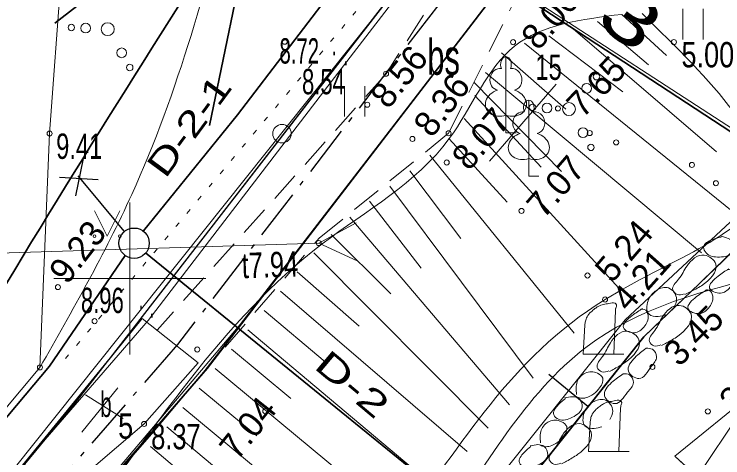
# Model space of a CAD drawing. Extents: x 514052 to 514314, y 297701 to 297876.
# Drawn here: x 514248.88 to 514262.86, y 297796.71 to 297805.47 of the extents above; entities that cross this region are included whole.
import ezdxf
from ezdxf.enums import TextEntityAlignment as Align

# ---------------------------------------------------------------- set-up
doc = ezdxf.new("R2010")
doc.units = 0
doc.header["$LTSCALE"] = 0.2
for name, pattern in [('DOT_DASHED', [7.7, 5, -1.2, 0.3, -1.2]), ('DOTTED', [1.5, 0.3, -1.2]), ('MEDIUM_DASHED', [4.5, 3, -1.5])]:
    doc.linetypes.add(name, pattern=pattern)
for name, color, linetype, lineweight in [('1', 7, 'Continuous', 13), ('11', 7, 'Continuous', 35), ('19', 7, 'Continuous', 25), ('25', 7, 'Continuous', 13), ('28', 7, 'Continuous', 13), ('3', 7, 'Continuous', 13), ('30', 7, 'Continuous', 13), ('35', 7, 'Continuous', 25), ('4', 7, 'Continuous', 13), ('5', 7, 'Continuous', 13), ('55', 7, 'Continuous', 13), ('56', 7, 'Continuous', 13), ('57', 7, 'DOTTED', 13), ('6', 7, 'Continuous', 13), ('61', 7, 'Continuous', 13), ('62', 7, 'Continuous', 13), ('63', 7, 'Continuous', 13)]:
    doc.layers.add(name, color=color, linetype=linetype, lineweight=lineweight)
for name, color, linetype in [('10', 7, 'Continuous'), ('12', 7, 'Continuous'), ('15', 7, 'Continuous'), ('8', 7, 'Continuous')]:
    doc.layers.add(name, color=color, linetype=linetype)

msp = doc.modelspace()

# ---------------------------------------------------------------- linework, layer by layer
at = {"layer": '1'}
for p, q in [((514260.862, 297805.466), (514261.747, 297804.65)), ((514260.382, 297805.324), (514261.389, 297804.471)), ((514259.903, 297805.181), (514262.732, 297802.751)), ((514259.424, 297805.039), (514260.887, 297803.934)), ((514258.944, 297804.897), (514263.46, 297801.234)), ((514258.488, 297804.703), (514259.759, 297803.593)), ((514258.178, 297804.315), (514262.439, 297800.756)), ((514257.964, 297803.863), (514259.276, 297802.447)), ((514257.752, 297803.41), (514260.804, 297800.061)), ((514257.457, 297803.009), (514258.604, 297801.754)), ((514257.079, 297802.682), (514259.927, 297799.171)), ((514256.685, 297802.375), (514257.691, 297801.041)), ((514256.285, 297802.075), (514259.118, 297798.277)), ((514255.886, 297801.774), (514256.907, 297800.454)), ((514255.498, 297801.458), (514258.648, 297797.755)), ((514255.13, 297801.12), (514256.31, 297799.945)), ((514254.791, 297800.753), (514258.23, 297797.292)), ((514254.46, 297800.378), (514255.685, 297799.307)), ((514254.132, 297800), (514257.81, 297796.829)), ((514253.807, 297799.62), (514255.009, 297798.603)), ((514253.484, 297799.238), (514257.177, 297796.134)), ((514253.163, 297798.855), (514254.335, 297797.88)), ((514252.844, 297798.47), (514256.52, 297795.422)), ((514252.525, 297798.085), (514253.664, 297797.141)), ((514252.206, 297797.701), (514255.837, 297794.686)), ((514251.886, 297797.316), (514252.993, 297796.394)), ((514251.565, 297796.933), (514255.194, 297793.878))]:
    msp.add_line(p, q, dxfattribs=at)
msp.add_circle((514254.16, 297803.109), 0.1827, dxfattribs=at)
msp.add_spline([(514260.862, 297805.466), (514258.749, 297804.839), (514257.459, 297803.011), (514254.953, 297800.933), (514250.105, 297795.245), (514240.136, 297784.718), (514236.07, 297778.812), (514235.246, 297774.955), (514233.92, 297771.109), (514234.456, 297764.804)], degree=3, dxfattribs=at)
at = {"layer": '11'}
msp.add_line((514256.643, 297807.328), (514264.954, 297801.867), dxfattribs=at)
for points in [[(514251.427, 297801.19), (514253.28, 297803.48), (514255.373, 297806.228)], [(514243.591, 297791.72), (514245.183, 297793.281), (514249.573, 297798.519), (514251.063, 297800.706)]]:
    msp.add_lwpolyline(points, dxfattribs=at)
at = {"layer": '19', "lineweight": 13}
msp.add_spline([(514243.205, 297765.058), (514242.936, 297773.769), (514245.025, 297781.038), (514246.54, 297783.925), (514249.054, 297787.013), (514257.225, 297795.21), (514260.154, 297798.886), (514267.863, 297801.516), (514273.305, 297805.826), (514276.583, 297807.615)], degree=3, dxfattribs=at)
at = {"layer": '25'}
for points in [[(514251.157, 297801.751), (514251.157, 297800.251), (514251.157, 297798.751)], [(514251.157, 297801.751), (514251.157, 297800.251), (514251.157, 297798.751)], [(514249.657, 297800.251), (514251.157, 297800.251), (514252.657, 297800.251)], [(514249.657, 297800.251), (514251.157, 297800.251), (514252.657, 297800.251)]]:
    msp.add_lwpolyline(points, dxfattribs=at)
at = {"layer": '28'}
msp.add_lwpolyline([(514255.622, 297801.347), (514254.884, 297800.949), (514255.645, 297800.598)], dxfattribs=at)
at = {"layer": '3'}
for p, q in [((514264.293, 297802.389), (514238.829, 297819.008)), ((514245.502, 297800.655), (514254.884, 297800.949))]:
    msp.add_line(p, q, dxfattribs=at)
at = {"layer": '30'}
msp.add_spline([(514249.384, 297798.494), (514251.195, 297801.909), (514253.241, 297808.298), (514253.999, 297811.552)], degree=3, dxfattribs=at)
at = {"layer": '35'}
msp.add_lwpolyline([(514231.97, 297771.331), (514233.541, 297774.128), (514233.667, 297780.485), (514240.255, 297787.177), (514246.843, 297793.868), (514250.774, 297798.68), (514254.387, 297803.352), (514256.058, 297805.511), (514258.694, 297808.915), (514260.151, 297809.248), (514268.632, 297811.186)], dxfattribs=at)
at = {"layer": '35', "lineweight": 35}
msp.add_lwpolyline([(514271.3, 297810.152), (514259.606, 297807.499), (514252.681, 297798.474), (514245.829, 297790.57), (514238.515, 297783.139), (514236.323, 297779.764), (514235.19, 297775.821), (514235.133, 297773.758), (514233.372, 297770.559)], dxfattribs=at)
at = {"layer": '4'}
for points in [[(514263.48, 297798.014), (514262.354, 297796.334), (514261.911, 297796.738)], [(514262.132, 297796.536), (514262.354, 297796.334), (514263.48, 297798.014), (514261.911, 297796.738)]]:
    msp.add_lwpolyline(points, close=True, dxfattribs=at)
at = {"layer": '5'}
for p, q in [((514262.068, 297804.972), (514262.068, 297805.572)), ((514262.468, 297804.972), (514262.468, 297805.572)), ((514258.579, 297804.626), (514258.579, 297803.473)), ((514258.669, 297804.394), (514258.668, 297804.395)), ((514255.392, 297803.448), (514255.392, 297804.048)), ((514255.792, 297803.448), (514255.792, 297804.048)), ((514259.029, 297803.772), (514259.029, 297802.619)), ((514258.579, 297803.473), (514258.579, 297803.126)), ((514259.119, 297803.54), (514259.118, 297803.541)), ((514258.579, 297803.126), (514258.779, 297803.126)), ((514259.029, 297802.619), (514259.029, 297802.272)), ((514259.029, 297802.272), (514259.229, 297802.272)), ((514260.704, 297798.757), (514260.738, 297799.622)), ((514260.704, 297798.757), (514260.104, 297798.757)), ((514260.704, 297798.757), (514260.904, 297798.757)), ((514260.807, 297796.832), (514260.841, 297797.697)), ((514260.807, 297796.832), (514260.207, 297796.832)), ((514260.807, 297796.832), (514261.007, 297796.832))]:
    msp.add_line(p, q, dxfattribs=at)
for points in [[(514250.462, 297801.587), (514250.712, 297801.087), (514250.962, 297801.587)], [(514260.135, 297799.33), (514260.104, 297798.757), (514260.404, 297798.757), (514260.704, 297798.757)], [(514260.238, 297797.405), (514260.207, 297796.832), (514260.507, 297796.832), (514260.807, 297796.832)]]:
    msp.add_lwpolyline(points, dxfattribs=at)
for centre, radius in [((514250.288, 297805.1939), 0.096), ((514250.7219, 297805.1731), 0.128), ((514250.0036, 297805.2074), 0.064), ((514250.9984, 297804.7063), 0.096), ((514251.1559, 297804.417), 0.064), ((514260.366, 297804.2345), 0.064), ((514260.1695, 297804.0028), 0.096), ((514259.1035, 297803.6294), 0.064), ((514259.388, 297803.6159), 0.096), ((514259.822, 297803.5952), 0.128), ((514260.0984, 297803.1283), 0.096), ((514260.2559, 297802.839), 0.064), ((514250.4621, 297801.0864), 0.028), ((514250.9621, 297801.0864), 0.0263)]:
    msp.add_circle(centre, radius, dxfattribs=at)
for centre, major_axis, ratio, start_param, end_param in [((514258.5794, 297804.4762), (0, -0.1499), 0.707107, 3.1453698, 5.2874846), ((514258.5785, 297804.4762), (0, -0.1499), 0.707107, 0.9957007, 3.1378155), ((514258.4507, 297804.1814), (-0.0387, -0.2124), 0.861323, 3.1415927, 6.2831853), ((514258.7072, 297804.1814), (0.0387, -0.2124), 0.861323, 6.2831853, 9.424778), ((514258.4894, 297803.7191), (0.3068, 0.0951), 0.814445, 1.5707963, 4.7520146), ((514258.6685, 297803.7191), (-0.3068, 0.0951), 0.814445, 1.5311707, 4.712389), ((514259.0294, 297803.6222), (0, -0.1499), 0.707107, 3.1453698, 5.2874846), ((514259.0285, 297803.6222), (0, -0.1499), 0.707107, 0.9957007, 3.1378155), ((514258.9007, 297803.3274), (-0.0387, -0.2124), 0.861323, 3.1415927, 6.2831853), ((514259.1572, 297803.3274), (0.0387, -0.2124), 0.861323, 6.2831853, 9.424778), ((514258.9394, 297802.8651), (0.3068, 0.0951), 0.814445, 1.5707963, 4.7520146), ((514259.1185, 297802.8651), (-0.3068, 0.0951), 0.814445, 1.5311707, 4.712389)]:
    msp.add_ellipse(centre, major_axis=major_axis, ratio=ratio, start_param=start_param, end_param=end_param, dxfattribs=at)
for points in [[(514260.738, 297799.622), (514260.742, 297799.653), (514260.745, 297799.664), (514260.76, 297799.726), (514260.73, 297799.761), (514260.608, 297799.755), (514260.504, 297799.737), (514260.398, 297799.698), (514260.333, 297799.654), (514260.258, 297799.59), (514260.178, 297799.492), (514260.147, 297799.403), (514260.135, 297799.329)], [(514260.841, 297797.697), (514260.845, 297797.728), (514260.848, 297797.739), (514260.863, 297797.801), (514260.833, 297797.836), (514260.711, 297797.83), (514260.607, 297797.812), (514260.501, 297797.773), (514260.436, 297797.729), (514260.361, 297797.665), (514260.281, 297797.567), (514260.25, 297797.478), (514260.238, 297797.404)]]:
    msp.add_spline(points, degree=3, dxfattribs=at)
at = {"layer": '55'}
msp.add_lwpolyline([(514217.339, 297769.84), (514231.97, 297771.331), (514233.541, 297774.128), (514233.602, 297778.964), (514248.877, 297796.499), (514258.817, 297808.985), (514270.863, 297811.577), (514272.894, 297813.849)], dxfattribs=at)
at = {"layer": '56'}
msp.add_lwpolyline([(514249.079, 297796.575), (514249.802, 297795.978), (514251.44, 297797.376), (514252.508, 297798.584), (514251.401, 297799.459)], close=True, dxfattribs=at)
at = {"layer": '57'}
msp.add_line((514249.886, 297798.666), (514258.975, 297809.539), dxfattribs=at)
at = {"layer": '6'}
for centre in [(514254.2148, 297804.9251), (514258.718, 297804.9162), (514261.892, 297804.9191), (514256.212, 297804.2922), (514255.8419, 297803.6801), (514259.6029, 297803.6072), (514249.5739, 297803.1122), (514256.7319, 297803.0042), (514257.448, 297803.1182), (514260.2319, 297803.1222), (514260.7529, 297802.9371), (514257.4109, 297802.5401), (514262.2479, 297802.4911), (514262.7215, 297802.1309), (514258.8849, 297801.5831), (514254.8839, 297800.9492), (514260.1879, 297800.3081), (514249.7388, 297800.0784), (514260.533, 297799.8342), (514250.462, 297799.4062), (514252.4889, 297798.8461), (514249.3839, 297798.4941), (514261.469, 297798.5021), (514253.8289, 297797.6282), (514262.562, 297797.624), (514251.4399, 297797.3761)]:
    msp.add_circle(centre, 0.05, dxfattribs=at)
at = {"layer": '61'}
msp.add_lwpolyline([(514246.843, 297793.868), (514250.081, 297797.789), (514258.694, 297808.915), (514270.983, 297811.723)], dxfattribs=at)
at = {"layer": '62'}
msp.add_spline([(514242.228, 297765.875), (514240.809, 297773.912), (514243.289, 297779.448), (514244.466, 297781.572), (514244.559, 297781.63), (514245.987, 297783.723), (514248.871, 297787.176), (514251.243, 297789.878), (514252.476, 297791.159), (514253.723, 297792.429), (514256.513, 297795.415), (514260.533, 297799.834), (514263.587, 297801.907), (514261.268, 297805.481)], degree=3, dxfattribs=at)
at = {"layer": '63'}
for p, q in [((514257.949, 297804.118), (514259.672, 297802.361)), ((514259.57, 297804.084), (514258.253, 297802.564)), ((514250.922, 297798.089), (514250.213, 297797.211)), ((514250.281, 297797.954), (514251.024, 297797.481))]:
    msp.add_line(p, q, dxfattribs=at)
at = {"layer": '63', "lineweight": 25}
for p, q in [((514250.237, 297802.622), (514250.089, 297801.883)), ((514249.769, 297802.253), (514250.532, 297802.204)), ((514251.049, 297801.185), (514250.138, 297802.278)), ((514260.196, 297797.718), (514259.422, 297798.35))]:
    msp.add_line(p, q, dxfattribs=at)
at = {"layer": '63', "lineweight": 35}
msp.add_line((514251.465, 297800.758), (514258.511, 297795.026), dxfattribs=at)
at = {"layer": '63'}
for points in [[(514240.25, 297797.788), (514240.461, 297794.955), (514244.254, 297792.763), (514245.158, 297793.439), (514249.384, 297798.494), (514249.574, 297803.112), (514249.804, 297806.229), (514250.567, 297808.046), (514251.305, 297808.79), (514254.642, 297812.211), (514253.566, 297813.059)], [(514241.033, 297787.835), (514244.727, 297791.588), (514248.123, 297795.505), (514251.519, 297799.422), (514255.132, 297804.131), (514258.746, 297808.841), (514264.857, 297810.227), (514270.968, 297811.614), (514271.3, 297810.152), (514259.609, 297807.499), (514256.144, 297802.987), (514253.336, 297799.341), (514249.255, 297794.522), (514245.829, 297790.57)], [(514246.248, 297791.053), (514247.856, 297792.907), (514251.587, 297797.176), (514252.569, 297798.349), (514254.104, 297800.332), (514255.107, 297801.628), (514257.105, 297804.234), (514259.609, 297807.499), (514265.761, 297808.894), (514271.304, 297810.15), (514273.327, 297806.65), (514267.17, 297803.809), (514264.799, 297803.032), (514260.928, 297799.431), (514257.141, 297794.684), (514253.744, 297790.866)]]:
    msp.add_lwpolyline(points, dxfattribs=at)
at = {"layer": '63', "linetype": 'MEDIUM_DASHED'}
for points in [[(514271.543, 297811.739), (514264.007, 297809.944), (514261.486, 297809.159), (514258.408, 297807.724), (514256.212, 297804.292), (514251.695, 297799.226)], [(514231.583, 297765.652), (514232.855, 297769.107), (514235.126, 297775.062), (514235.802, 297779.27), (514240.035, 297784.801), (514250.098, 297795.488), (514254.893, 297801.043), (514257.448, 297803.118), (514259.485, 297807.223), (514261.814, 297808.455), (514265.145, 297808.86), (514272.105, 297811.112)]]:
    msp.add_lwpolyline(points, dxfattribs=at)
at = {"layer": '63', "linetype": 'DOT_DASHED', "lineweight": 25}
for points in [[(514271.134, 297810.883), (514259.176, 297808.17), (514252.1, 297798.948), (514245.278, 297791.079), (514237.927, 297783.611), (514235.633, 297780.079), (514234.443, 297775.937), (514234.388, 297773.96), (514232.332, 297770.225), (514229.92, 297766.887)], [(514241.744, 297765.925), (514242.057, 297774.207), (514242.797, 297776.707), (514244.225, 297779.218), (514245.964, 297781.323), (514250.712, 297786.706), (514257.523, 297794.362), (514261.299, 297799.094), (514264.423, 297802.109), (514265.043, 297802.596), (514265.222, 297802.656), (514267.352, 297803.342), (514273.537, 297806.201)]]:
    msp.add_lwpolyline(points, dxfattribs=at)
at = {"layer": '63', "lineweight": 35}
for points in [[(514249.676, 297805.292), (514253.805, 297808.49), (514252.731, 297803.27)], [(514241.744, 297765.925), (514242.057, 297774.207), (514242.797, 297776.707), (514244.225, 297779.218), (514245.094, 297780.271), (514245.964, 297781.323), (514248.338, 297784.015), (514250.712, 297786.706), (514254.118, 297790.534), (514257.523, 297794.362), (514259.411, 297796.728), (514261.299, 297799.094), (514262.861, 297800.601), (514264.423, 297802.109), (514265.043, 297802.596), (514267.352, 297803.342), (514273.537, 297806.201)]]:
    msp.add_lwpolyline(points, dxfattribs=at)
at = {"layer": '63', "lineweight": 25}
msp.add_circle((514251.2418, 297800.9459), 0.3, dxfattribs=at)
at = {"layer": '63', "lineweight": 35}
msp.add_spline([(514235.586, 297788.069), (514238.834, 297789.344), (514246.139, 297795.966), (514248.394, 297799.596), (514253.835, 297808.327)], degree=3, dxfattribs=at)
at = {"layer": '63'}
for points in [[(514262.815, 297801.085), (514263.061, 297800.954), (514263.055, 297800.779), (514262.791, 297800.673), (514262.527, 297800.755), (514262.479, 297800.87), (514262.651, 297801.017), (514262.823, 297801.067)], [(514262.096, 297799.946), (514261.957, 297799.934), (514261.87, 297800.023), (514261.986, 297800.234), (514262.151, 297800.499), (514262.492, 297800.711), (514262.717, 297800.532), (514262.437, 297800.107), (514262.21, 297799.983), (514262.108, 297799.933)], [(514262.973, 297800.438), (514262.764, 297800.295), (514262.596, 297800.06), (514262.814, 297799.96), (514262.998, 297800.069), (514263.082, 297800.304), (514263.007, 297800.421), (514262.948, 297800.421)], [(514261.888, 297799.675), (514261.946, 297799.841), (514261.786, 297800.062), (514261.548, 297800.015), (514261.381, 297799.808), (514261.402, 297799.543), (514261.58, 297799.5), (514261.731, 297799.531)], [(514262.549, 297800.033), (514262.34, 297799.89), (514262.172, 297799.655), (514262.39, 297799.555), (514262.574, 297799.664), (514262.658, 297799.899), (514262.583, 297800.016), (514262.524, 297800.016)], [(514261.637, 297798.936), (514261.499, 297798.918), (514261.408, 297799.003), (514261.514, 297799.219), (514261.667, 297799.491), (514261.999, 297799.718), (514262.231, 297799.549), (514261.971, 297799.112), (514261.749, 297798.978), (514261.65, 297798.923)], [(514261.274, 297799.656), (514261.065, 297799.513), (514260.897, 297799.278), (514261.115, 297799.178), (514261.299, 297799.287), (514261.383, 297799.522), (514261.308, 297799.639), (514261.249, 297799.639)], [(514260.609, 297798.425), (514260.471, 297798.407), (514260.38, 297798.492), (514260.486, 297798.708), (514260.639, 297798.98), (514260.971, 297799.207), (514261.203, 297799.038), (514260.943, 297798.601), (514260.721, 297798.467), (514260.622, 297798.412)], [(514261.342, 297798.87), (514261.122, 297798.685), (514260.995, 297798.416), (514261.201, 297798.273), (514261.445, 297798.509), (514261.55, 297798.703), (514261.469, 297798.85), (514261.342, 297798.87)], [(514259.97, 297797.959), (514259.986, 297798.212), (514260.143, 297798.382), (514260.384, 297798.377), (514260.487, 297798.281), (514260.407, 297798.064), (514260.272, 297797.945), (514260.049, 297797.886), (514259.972, 297797.91)], [(514260.892, 297798.368), (514260.664, 297798.193), (514260.525, 297797.93), (514260.725, 297797.778), (514260.979, 297798.003), (514261.093, 297798.192), (514261.018, 297798.343), (514260.892, 297798.368)], [(514259.736, 297797.891), (514260.014, 297797.876), (514260.084, 297797.715), (514259.889, 297797.507), (514259.615, 297797.471), (514259.523, 297797.555), (514259.617, 297797.76), (514259.751, 297797.878)], [(514260.629, 297797.464), (514260.687, 297797.63), (514260.527, 297797.851), (514260.289, 297797.804), (514260.122, 297797.597), (514260.143, 297797.332), (514260.321, 297797.289), (514260.472, 297797.32)], [(514259.26, 297797.003), (514259.276, 297797.256), (514259.433, 297797.426), (514259.674, 297797.421), (514259.777, 297797.325), (514259.697, 297797.108), (514259.562, 297796.989), (514259.339, 297796.93), (514259.262, 297796.954)], [(514259.663, 297796.6), (514259.525, 297796.582), (514259.434, 297796.667), (514259.54, 297796.883), (514259.693, 297797.155), (514260.025, 297797.382), (514260.257, 297797.213), (514259.997, 297796.776), (514259.775, 297796.642), (514259.676, 297796.587)], [(514259.056, 297796.945), (514259.334, 297796.93), (514259.404, 297796.769), (514259.209, 297796.561), (514258.935, 297796.525), (514258.843, 297796.609), (514258.937, 297796.814), (514259.071, 297796.932)]]:
    msp.add_spline(points, degree=3, dxfattribs=at)

# ---------------------------------------------------------------- texts
at = {"layer": '10', "width": 0.65}
msp.add_text('bs', height=0.7, dxfattribs=at).set_placement((514257.349, 297804.272), align=Align.CENTER)
at = {"layer": '11'}
for s, rotation, width, p in [('t7.94', 1.795, 0.75, (514253.9292, 297800.2707)), ('D-2', 319.946, 1.5, (514255.3866, 297797.969))]:
    msp.add_text(s, height=0.5, rotation=rotation, dxfattribs=dict(at, width=width)).set_placement(p, align=Align.CENTER)
at = {"layer": '12'}
for s, width, p in [(' 15', 0.7, (514259.029, 297804.172)), (' 5', 0.8, (514250.778, 297797.084))]:
    msp.add_text(s, height=0.5, dxfattribs=dict(at, width=width)).set_placement(p)
at = {"layer": '15', "width": 0.6}
msp.add_text('b', height=0.5, dxfattribs=at).set_placement((514250.575, 297797.513))
at = {"layer": '63'}
for s, height, rotation, width, p in [('D-3', 1, 323.374, 1.45, (514259.9227, 297805.597)), ('D-2-1', 0.5, 53.597, 1.35, (514252.5286, 297803.1141))]:
    msp.add_text(s, height=height, rotation=rotation, dxfattribs=dict(at, width=width)).set_placement(p, align=Align.CENTER)
at = {"layer": '8'}
for s, rotation, p in [(' 8.00', 49.596, (514259.099, 297804.592)), (' 8.56', 51.117, (514256.138, 297803.429)), (' 7.65', 46.428, (514259.965, 297803.263)), (' 8.36', 53.061, (514257.007, 297802.86)), (' 8.07', 49.339, (514257.728, 297802.214)), (' 7.07', 49.117, (514259.201, 297801.271)), (' 9.23', 52.106, (514249.807, 297799.963)), (' 5.24', 49.445, (514260.552, 297799.999)), (' 4.21', 48.26, (514260.875, 297799.43)), (' 3.45', 45.114, (514261.867, 297798.355)), (' 3.31', 46.023, (514262.972, 297797.429)), (' 7.04', 51.541, (514253.162, 297796.487))]:
    msp.add_text(s, height=0.5, rotation=rotation, dxfattribs=at).set_placement(p)
for s, width, p in [('8.72', 0.6, (514254.11, 297804.494)), (' 5.00', 0.8, (514261.892, 297804.419)), ('.', 0.5, (514255.142, 297804.654)), ('.', 0.5, (514255.373, 297804.458)), ('8.54', 0.65, (514254.555, 297803.888)), (' 9.41', 0.7, (514249.574, 297802.612)), ('8.96', 0.65, (514250.193, 297799.566)), ('.', 0.5, (514251.332, 297799.637)), ('.', 0.5, (514251.546, 297799.477)), (' 8.37', 0.75, (514251.44, 297796.876))]:
    msp.add_text(s, height=0.5, dxfattribs=dict(at, width=width)).set_placement(p)

doc.saveas('drawing.dxf')
